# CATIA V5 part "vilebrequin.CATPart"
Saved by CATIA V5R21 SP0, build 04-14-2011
Part number: vilebrequin
Material "Laiton": density 8216 kg/m3, Young's modulus 1.31e+11 Pa, Poisson ratio 0.35, thermal expansion 1.67e-05 1/K
Bounding box of the stored display mesh (mm): x -12.5 to 12.5, y -31 to 31, z -13.25 to 13.205
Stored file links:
  C:\Users\Olivier\Desktop\redaction CATIA (local)\pompe à moteur de ventilation refait\vilebrequin.CATPart
  C:\Program Files\Dassault Systemes\B21\win_b64\startup\materials\French\Catalog.CATMaterial
  C:\Users\Olivier\Desktop\redaction CATIA (local)\pompe à moteur de ventilation refait\Pompe_a_moteur_de_ventilation.CATProduct
  C:\Users\Olivier\Desktop\redaction CATIA (local)\pompe à moteur de ventilation refait\Ecrou a collerette M5.CATPart
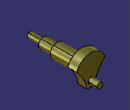
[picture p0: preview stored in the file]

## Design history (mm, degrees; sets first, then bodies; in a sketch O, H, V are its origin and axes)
Body1 (main body), material "Laiton"
  Sketch1 on yz-plane, origin (0, 0, 0), H (0, 1, 0), V (0, 0, 1)
    line L1 (-31, 0) -> (-31, 2.5)
    point P1 (-31, 0)
    line L2 (-31, 2.5) -> (-19, 2.5)
    line L3 (-19, 2.5) -> (-19, 4.5)
    line L4 (-19, 4.5) -> (-7, 4.5)
    line L5 (-7, 4.5) -> (-7, 6.25)
    line L6 (-7, 6.25) -> (15, 6.25)
    line L7 (15, 6.25) -> (15, 4.25)
    point P8 (15, 4.25)
    point P9 (23, 4.25)
    point P10 (23, 2.5)
    point P11 (31, 2.5)
    point P12 (31, 0)
    line L8 (15, 0) -> (-31, 0)
    line L9 (15, 4.25) -> (15, 0)
    length L2 = 12
    distance L5 L1 = 24
    length L1 = 2.5
    distance L4 L8 = 4.5
    distance L6 L8 = 6.25
    distance P12 P1 = 62
    distance P8 P9 = 8
    distance P10 P11 = 8
    coincidence: P1 H, P12 H
    vertical: L1 V, L3 V, L5 V, L7 V, L9 V
    horizontal: L2 H, L4 H, L6 H, L8 H
  Shaft1: profile Sketch1, axis Sketch1.H, angle 360
  Sketch2 on face of Shaft1 from Sketch1.L7, origin (0, 15, 0), H (-1, 0, 0), V (0, 0, 1)
    circle A1 centre (0, 0) radius 4.25
    arc A2 centre (0, 0) radius 13.25 from (12.5, 4.3946) to (-12.5, 4.3946) ccw
    point P1 (-3.5, -12.7794)
    point P2 (3.5, -12.7794)
    arc A3 centre (33.1466, -17.3704) radius 30 from (3.5, -12.7794) to (12.5, 4.3946) cw
    point P4 (12.5, 4.3946)
    point P5 (-12.5, 4.3946)
    point P6 (-3.5, -12.7794)
    arc A4 centre (-33.1466, -17.3704) radius 30 from (-3.5, -12.7794) to (-12.5, 4.3946) ccw
    arc A5 centre (0, 0) radius 13.25 from (-3.5, -12.7794) to (3.5, -12.7794) ccw
    circle A6 centre (0, -8) radius 2.5
    point P8 (0, -8)
    radius A2 = 13.25
    distance P1 P2 = 7
    distance P8 H = 8
    radius A1 = 4.25
    radius A6 = 2.5
    radius A4 = 30
    distance P4 P5 = 25
    coincidence: P1 A2, A2 A5, P8 V, P1 P6
    symmetry: P4 P5 V, P2 P6 V, A3 A4 V
  MultiPad1: profile Sketch2, domains (length 8; length 16; length 8)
